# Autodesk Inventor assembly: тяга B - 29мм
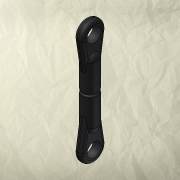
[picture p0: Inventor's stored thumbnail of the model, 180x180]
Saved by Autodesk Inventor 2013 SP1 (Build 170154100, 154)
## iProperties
Created: 2012-02
Part Number: тяга B - 29мм
Document SubType Name: Assembly
Designer: WH
ipwModelExtentsX: 4.4
ipwModelExtentsY: 7
ipwModelExtentsZ: 36
ipwMass: N/V
ipwArea: N/V
ipwVolume: N/V
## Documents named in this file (2)
- G:\IV2k13-Forum\Rotor\Koppel B - 29mm.iam
- G:\IV2k13-Forum\Rotor\Kugelpfanne 2.ipt
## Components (2 placed, 1 different names)
1. Kugelpfanne 2.ipt:1
2. Kugelpfanne 2.ipt:2
